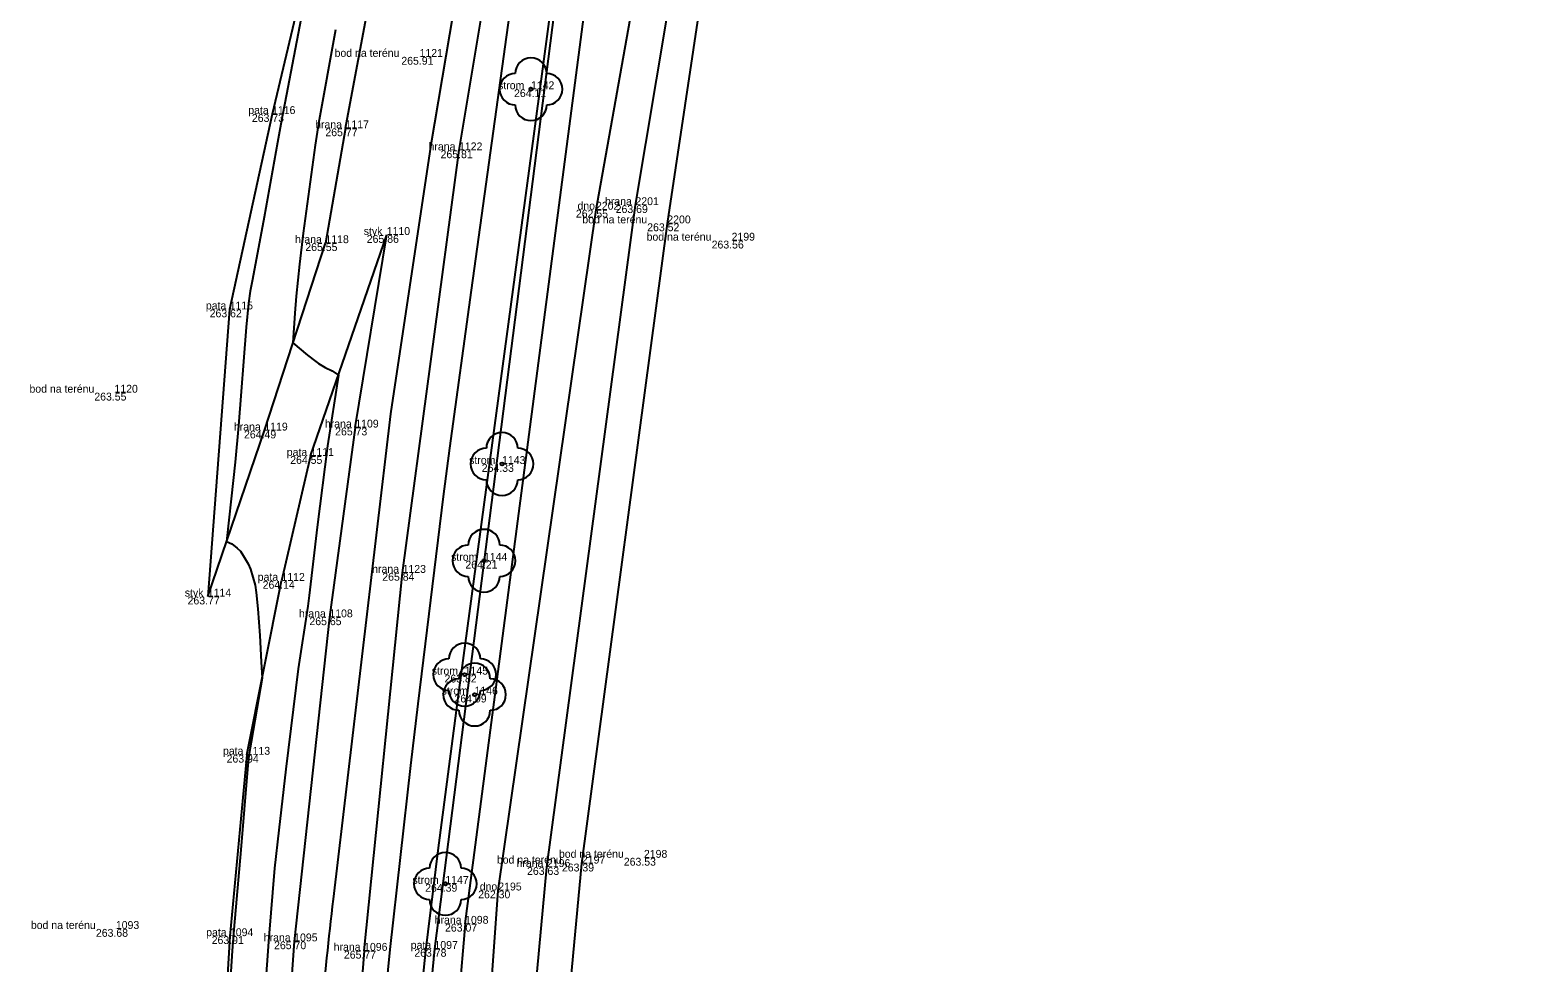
# Model space of a CAD drawing. Extents: x -567962 to -566460, y -1093720 to -1089838.
# Drawn here: x -567311.7 to -567215.7, y -1091389.9 to -1091330.5 of the extents above; entities that cross this region are included whole.
import ezdxf

# ---------------------------------------------------------------- set-up
doc = ezdxf.new("R2010")
doc.units = 0
for name, color, linetype in [('0_osa hráze', 7, 'Continuous'), ('bod_znacka', 7, 'Continuous'), ('cislo_bodu', 7, 'Continuous'), ('Doměření - kraj pole', 7, 'Continuous'), ('hlavni_vrst', 7, 'Continuous'), ('hrana_L', 7, 'Continuous'), ('kod_bodu', 7, 'Continuous'), ('norm_vrst', 7, 'Continuous'), ('stromy', 7, 'Continuous'), ('vyska_bodu', 7, 'Continuous')]:
    doc.layers.add(name, color=color, linetype=linetype)

msp = doc.modelspace()

# ---------------------------------------------------------------- linework, layer by layer
at = {"layer": '0_osa hráze'}
msp.add_lwpolyline([(-567215.714, -1090962.554), (-567217.549, -1090969.598), (-567222.391, -1090991.652), (-567228.271, -1091022.144), (-567274.096, -1091269.912), (-567281.877, -1091312.435), (-567286.177, -1091337.802), (-567288.735, -1091354.935), (-567292.39, -1091385.821)], dxfattribs=at)
msp.add_arc((-566984.791, -1091422.198), 309.743, 173.25558, 176.03141, dxfattribs=at)
at = {"layer": 'bod_znacka'}
for p, q in [((-567286.89, -1091332.2), (-567286.89, -1091332.2)), ((-567279.8, -1091334.26), (-567279.8, -1091334.26)), ((-567296.28, -1091335.84), (-567296.28, -1091335.84)), ((-567291.6, -1091336.75), (-567291.6, -1091336.75)), ((-567284.38, -1091338.15), (-567284.38, -1091338.15)), ((-567275.66, -1091341.93), (-567275.66, -1091341.93)), ((-567273.15, -1091341.64), (-567273.15, -1091341.64)), ((-567271.12, -1091342.8), (-567271.12, -1091342.8)), ((-567288.98, -1091343.54), (-567288.98, -1091343.54)), ((-567267.03, -1091343.9), (-567267.03, -1091343.9)), ((-567292.88, -1091344.06), (-567292.88, -1091344.06)), ((-567298.98, -1091348.28), (-567298.98, -1091348.28)), ((-567306.31, -1091353.58), (-567306.31, -1091353.58)), ((-567296.77, -1091355.99), (-567296.77, -1091355.99)), ((-567290.98, -1091355.8), (-567290.98, -1091355.8)), ((-567293.83, -1091357.61), (-567293.83, -1091357.61)), ((-567281.64, -1091358.12), (-567281.64, -1091358.12)), ((-567287.97, -1091365.05), (-567287.97, -1091365.05)), ((-567282.79, -1091364.28), (-567282.79, -1091364.28)), ((-567295.68, -1091365.56), (-567295.68, -1091365.56)), ((-567300.37, -1091366.56), (-567300.37, -1091366.56)), ((-567292.63, -1091367.88), (-567292.63, -1091367.88)), ((-567284.02, -1091371.53), (-567284.02, -1091371.53)), ((-567283.39, -1091372.8), (-567283.39, -1091372.8)), ((-567297.89, -1091376.63), (-567297.89, -1091376.63)), ((-567272.61, -1091383.19), (-567272.61, -1091383.19)), ((-567278.78, -1091383.78), (-567278.78, -1091383.78)), ((-567276.56, -1091383.56), (-567276.56, -1091383.56)), ((-567285.25, -1091384.85), (-567285.25, -1091384.85)), ((-567281.88, -1091385.27), (-567281.88, -1091385.27)), ((-567306.22, -1091387.72), (-567306.22, -1091387.72)), ((-567283.99, -1091387.39), (-567283.99, -1091387.39)), ((-567298.96, -1091388.18), (-567298.96, -1091388.18)), ((-567294.87, -1091388.51), (-567294.87, -1091388.51)), ((-567285.94, -1091388.99), (-567285.94, -1091388.99)), ((-567290.42, -1091389.11), (-567290.42, -1091389.11))]:
    msp.add_line(p, q, dxfattribs=at)
at = {"layer": 'Doměření - kraj pole'}
msp.add_lwpolyline([(-567257.475, -1091769.846), (-567265.06, -1091716.84), (-567271.4, -1091685.39), (-567277.57, -1091653.16), (-567282.77, -1091606.25), (-567283.94, -1091587.31), (-567282.43, -1091491.21), (-567281.67, -1091450.14), (-567280.3, -1091423.49), (-567276.56, -1091383.56), (-567271.12, -1091342.8), (-567265.61, -1091306.08), (-567257.61, -1091256.68), (-567252.66, -1091230.206)], dxfattribs=at)
at = {"layer": 'hlavni_vrst'}
for points in [[(-567290.074, -1091402.407), (-567288.751, -1091389.027), (-567287.437, -1091377.305), (-567286.973, -1091373.388), (-567285.359, -1091360.183), (-567284.966, -1091357.103), (-567283.594, -1091347.05), (-567280.777, -1091326.787), (-567280.37, -1091323.895), (-567279.976, -1091321.396), (-567279.213, -1091316.884), (-567277.707, -1091308.422), (-567277.254, -1091305.946), (-567276.872, -1091304.04), (-567275.44, -1091297.066), (-567274.514, -1091292.454), (-567273.654, -1091288.041), (-567270.19, -1091269.818)], [(-567292.243, -1091330.472), (-567293.329, -1091336.439), (-567293.541, -1091337.828), (-567294.301, -1091343.43), (-567294.539, -1091345.39), (-567294.747, -1091347.435), (-567294.835, -1091348.525), (-567294.947, -1091350.399), (-567294.033, -1091351.183), (-567293.499, -1091351.603), (-567293.316, -1091351.726), (-567292.888, -1091351.968), (-567292.457, -1091352.19), (-567292.059, -1091352.471), (-567292.748, -1091356.96), (-567293.406, -1091362.133), (-567293.923, -1091366.492), (-567294.011, -1091367.17), (-567294.607, -1091371.164), (-567295.399, -1091377.54), (-567295.857, -1091381.426), (-567296.116, -1091383.859), (-567296.481, -1091388.25), (-567297.798, -1091406.423)]]:
    msp.add_lwpolyline(points, dxfattribs=at)
at = {"layer": 'hrana_L'}
for p, q in [((-567275.47, -1091306.87), (-567285.94, -1091388.99)), ((-567283.99, -1091387.39), (-567273.54, -1091307.53)), ((-567291.6, -1091336.75), (-567288.51, -1091320.09)), ((-567292.86, -1091321.4), (-567296.28, -1091335.84)), ((-567284.38, -1091338.15), (-567281.97, -1091323.81)), ((-567296.28, -1091335.84), (-567298.98, -1091348.28)), ((-567291.6, -1091336.75), (-567292.88, -1091344.06)), ((-567287.97, -1091365.05), (-567284.38, -1091338.15)), ((-567293.83, -1091357.61), (-567288.98, -1091343.54)), ((-567290.98, -1091355.8), (-567288.98, -1091343.54)), ((-567296.77, -1091355.99), (-567292.88, -1091344.06)), ((-567298.98, -1091348.28), (-567300.37, -1091366.56)), ((-567300.37, -1091366.56), (-567296.77, -1091355.99)), ((-567290.98, -1091355.8), (-567292.63, -1091367.88)), ((-567293.83, -1091357.61), (-567295.68, -1091365.56)), ((-567290.42, -1091389.11), (-567287.97, -1091365.05)), ((-567297.89, -1091376.63), (-567295.68, -1091365.56)), ((-567292.63, -1091367.88), (-567294.87, -1091388.51)), ((-567297.89, -1091376.63), (-567298.96, -1091388.18)), ((-567283.99, -1091387.39), (-567287.28, -1091424.81)), ((-567298.96, -1091388.18), (-567301.25, -1091425.23)), ((-567294.87, -1091388.51), (-567297.56, -1091425.27)), ((-567285.94, -1091388.99), (-567289.44, -1091424.96)), ((-567290.42, -1091389.11), (-567293.31, -1091425.54))]:
    msp.add_line(p, q, dxfattribs=at)
for points in [[(-567259.536, -1091769.583), (-567267.06, -1091718.28), (-567273.44, -1091685.18), (-567279.67, -1091653.51), (-567285.46, -1091606.32), (-567286.7, -1091587.2), (-567284.69, -1091490.41), (-567283.78, -1091449.87), (-567282.54, -1091424.45), (-567278.78, -1091383.78), (-567273.15, -1091341.64), (-567267.14, -1091305.78), (-567258.66, -1091256.72), (-567254.64, -1091232.23), (-567240.38, -1091148.66)], [(-567261.58, -1091768.889), (-567269.05, -1091719.43), (-567275.12, -1091685.08), (-567281.42, -1091653.8), (-567287.56, -1091606.69), (-567288.64, -1091587.56), (-567287.08, -1091491.97), (-567286.43, -1091448.99), (-567284.64, -1091424.04), (-567281.88, -1091385.27), (-567275.66, -1091341.93), (-567269.17, -1091305.64), (-567264.83, -1091271.45)]]:
    msp.add_lwpolyline(points, dxfattribs=at)
at = {"layer": 'norm_vrst'}
for points in [[(-567287.853, -1091402.243), (-567286.483, -1091389.115), (-567285.704, -1091382.717), (-567284.362, -1091372.513), (-567279.614, -1091337.241), (-567275.639, -1091307.398), (-567275.58, -1091307.028), (-567275.165, -1091304.934), (-567272.862, -1091293.477), (-567268.336, -1091270.732)], [(-567294.14, -1091328.26), (-567295.471, -1091335.14), (-567295.643, -1091336.013), (-567295.94, -1091337.645), (-567296.781, -1091342.399), (-567297.534, -1091346.372), (-567297.667, -1091347.125), (-567297.77, -1091347.877), (-567297.921, -1091349.414), (-567298.422, -1091355.698), (-567298.635, -1091358), (-567298.876, -1091360.335), (-567299.177, -1091363.056), (-567298.832, -1091363.208), (-567298.502, -1091363.469), (-567298.296, -1091363.666), (-567298.116, -1091363.935), (-567297.799, -1091364.48), (-567297.642, -1091364.818), (-567297.354, -1091365.831), (-567297.29, -1091366.309), (-567297.193, -1091367.342), (-567297.067, -1091369.035), (-567296.963, -1091370.705), (-567296.917, -1091371.757), (-567297.619, -1091375.82), (-567297.75, -1091376.672), (-567297.832, -1091377.551), (-567298.259, -1091382.694), (-567298.718, -1091387.76), (-567298.824, -1091389.124), (-567301.032, -1091423.471)]]:
    msp.add_lwpolyline(points, dxfattribs=at)
at = {"layer": 'stromy'}
for centre in [(-567279.8, -1091334.26), (-567281.64, -1091358.12), (-567282.79, -1091364.28), (-567284.02, -1091371.53), (-567283.39, -1091372.8), (-567285.25, -1091384.85)]:
    msp.add_circle(centre, 0.1, dxfattribs=at)
for centre, start, end in [((-567279.8, -1091333.26), 0, 180), ((-567280.8, -1091334.26), 90, 270), ((-567278.8, -1091334.26), 270, 90), ((-567279.8, -1091335.26), 180, 0), ((-567281.64, -1091357.12), 0, 180), ((-567282.64, -1091358.12), 90, 270), ((-567280.64, -1091358.12), 270, 90), ((-567281.64, -1091359.12), 180, 0), ((-567282.79, -1091363.28), 0, 180), ((-567283.79, -1091364.28), 90, 270), ((-567281.79, -1091364.28), 270, 90), ((-567282.79, -1091365.28), 180, 0), ((-567284.02, -1091370.53), 0, 180), ((-567285.02, -1091371.53), 90, 270), ((-567283.39, -1091371.8), 0, 180), ((-567283.02, -1091371.53), 270, 90), ((-567284.39, -1091372.8), 90, 270), ((-567284.02, -1091372.53), 180, 0), ((-567282.39, -1091372.8), 270, 90), ((-567283.39, -1091373.8), 180, 0), ((-567285.25, -1091383.85), 0, 180), ((-567286.25, -1091384.85), 90, 270), ((-567284.25, -1091384.85), 270, 90), ((-567285.25, -1091385.85), 180, 0)]:
    msp.add_arc(centre, 1, start, end, dxfattribs=at)

# ---------------------------------------------------------------- texts
at = {"layer": 'cislo_bodu'}
for s, p in [('1121', (-567286.89, -1091332.2)), ('1142', (-567279.8, -1091334.26)), ('1116', (-567296.28, -1091335.84)), ('1117', (-567291.6, -1091336.75)), ('1122', (-567284.38, -1091338.15)), ('2202', (-567275.66, -1091341.93)), ('2201', (-567273.15, -1091341.64)), ('2200', (-567271.12, -1091342.8)), ('1118', (-567292.88, -1091344.06)), ('1110', (-567288.98, -1091343.54)), ('2199', (-567267.03, -1091343.9)), ('1115', (-567298.98, -1091348.28)), ('1120', (-567306.31, -1091353.58)), ('1119', (-567296.77, -1091355.99)), ('1109', (-567290.98, -1091355.8)), ('1111', (-567293.83, -1091357.61)), ('1143', (-567281.64, -1091358.12)), ('1144', (-567282.79, -1091364.28)), ('1112', (-567295.68, -1091365.56)), ('1123', (-567287.97, -1091365.05)), ('1114', (-567300.37, -1091366.56)), ('1108', (-567292.63, -1091367.88)), ('1145', (-567284.02, -1091371.53)), ('1146', (-567283.39, -1091372.8)), ('1113', (-567297.89, -1091376.63)), ('2196', (-567278.78, -1091383.78)), ('2197', (-567276.56, -1091383.56)), ('2198', (-567272.61, -1091383.19)), ('1147', (-567285.25, -1091384.85)), ('2195', (-567281.88, -1091385.27)), ('1098', (-567283.99, -1091387.39)), ('1093', (-567306.22, -1091387.72)), ('1094', (-567298.96, -1091388.18)), ('1095', (-567294.87, -1091388.51)), ('1096', (-567290.42, -1091389.11)), ('1097', (-567285.94, -1091388.99))]:
    msp.add_text(s, height=0.5, dxfattribs=at).set_placement(p)
at = {"layer": 'kod_bodu'}
for s, p in [('bod na terénu', (-567292.299, -1091332.2)), ('strom', (-567281.894, -1091334.26)), ('pata', (-567297.792, -1091335.84)), ('hrana', (-567293.537, -1091336.75)), ('hrana', (-567286.317, -1091338.15)), ('dno', (-567276.841, -1091341.93)), ('hrana', (-567275.087, -1091341.64)), ('bod na terénu', (-567276.529, -1091342.8)), ('hrana', (-567294.817, -1091344.06)), ('styk', (-567290.444, -1091343.54)), ('bod na terénu', (-567272.439, -1091343.9)), ('pata', (-567300.492, -1091348.28)), ('bod na terénu', (-567311.719, -1091353.58)), ('hrana', (-567298.707, -1091355.99)), ('hrana', (-567292.917, -1091355.8)), ('pata', (-567295.342, -1091357.61)), ('strom', (-567283.734, -1091358.12)), ('strom', (-567284.884, -1091364.28)), ('hrana', (-567289.907, -1091365.05)), ('styk', (-567301.834, -1091366.56)), ('pata', (-567297.192, -1091365.56)), ('hrana', (-567294.567, -1091367.88)), ('strom', (-567286.114, -1091371.53)), ('strom', (-567285.484, -1091372.8)), ('pata', (-567299.402, -1091376.63)), ('bod na terénu', (-567281.969, -1091383.56)), ('hrana', (-567280.717, -1091383.78)), ('bod na terénu', (-567278.019, -1091383.19)), ('strom', (-567287.344, -1091384.85)), ('dno', (-567283.061, -1091385.27)), ('hrana', (-567285.927, -1091387.39)), ('bod na terénu', (-567311.629, -1091387.72)), ('pata', (-567300.472, -1091388.18)), ('hrana', (-567296.807, -1091388.51)), ('hrana', (-567292.357, -1091389.11)), ('pata', (-567287.452, -1091388.99))]:
    msp.add_text(s, height=0.5, dxfattribs=at).set_placement(p)
at = {"layer": 'vyska_bodu'}
for s, p in [('265.91', (-567288.051, -1091332.7)), ('264.11', (-567280.877, -1091334.76)), ('263.73', (-567297.563, -1091336.34)), ('265.77', (-567292.885, -1091337.25)), ('265.81', (-567285.553, -1091338.65)), ('262.55', (-567276.941, -1091342.43)), ('263.69', (-567274.408, -1091342.14)), ('263.52', (-567272.401, -1091343.3)), ('265.86', (-567290.25, -1091344.04)), ('263.56', (-567268.3, -1091344.4)), ('265.55', (-567294.161, -1091344.56)), ('263.62', (-567300.25, -1091348.78)), ('263.55', (-567307.591, -1091354.08)), ('264.49', (-567298.063, -1091356.49)), ('265.73', (-567292.263, -1091356.3)), ('264.55', (-567295.123, -1091358.11)), ('264.33', (-567282.933, -1091358.62)), ('265.84', (-567289.263, -1091365.55)), ('264.21', (-567283.975, -1091364.78)), ('264.14', (-567296.877, -1091366.06)), ('263.77', (-567301.655, -1091367.06)), ('265.65', (-567293.9, -1091368.38)), ('263.82', (-567285.301, -1091372.03)), ('264.09', (-567284.669, -1091373.3)), ('263.94', (-567299.171, -1091377.13)), ('263.53', (-567273.891, -1091383.69)), ('263.63', (-567280.05, -1091384.28)), ('263.39', (-567277.83, -1091384.06)), ('264.39', (-567286.531, -1091385.35)), ('262.30', (-567283.159, -1091385.77)), ('263.68', (-567307.49, -1091388.22)), ('263.07', (-567285.271, -1091387.89)), ('263.91', (-567300.121, -1091388.68)), ('265.70', (-567296.151, -1091389.01)), ('263.78', (-567287.223, -1091389.49)), ('265.77', (-567291.705, -1091389.61))]:
    msp.add_text(s, height=0.5, dxfattribs=at).set_placement(p)

doc.saveas('drawing.dxf')
